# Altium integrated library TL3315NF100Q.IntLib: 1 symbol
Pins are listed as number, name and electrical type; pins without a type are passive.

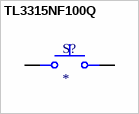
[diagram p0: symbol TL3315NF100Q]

## TL3315NF100Q
designator S?
Tactile Switch SPST-NO Top Actuated Surface Mount; MF: E-Switch; MP: TL3315NF100Q
footprint SW_TL3315NF100Q
pins: 1, 2 1, 3, 4 3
